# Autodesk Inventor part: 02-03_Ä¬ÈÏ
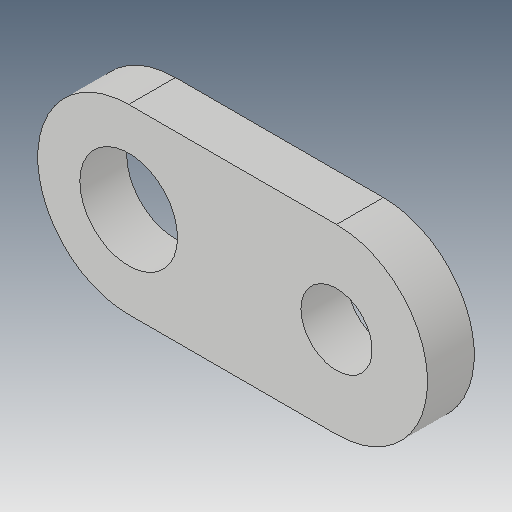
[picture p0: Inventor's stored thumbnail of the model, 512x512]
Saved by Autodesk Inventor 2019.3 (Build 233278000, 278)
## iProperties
Created: 2010-06
Part Number: 02-03_Ä¬ÈÏ
Material: Ogólny
Document SubType Name: Modeling
Designer: CADENGINEERING4
Density: 1 g/cm^3
Appearance: Domyślna
Author: CADENGINEERING4
Revision Number: ÈÎºÎ
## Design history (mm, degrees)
feature "NONE"
node "Bryła1"
